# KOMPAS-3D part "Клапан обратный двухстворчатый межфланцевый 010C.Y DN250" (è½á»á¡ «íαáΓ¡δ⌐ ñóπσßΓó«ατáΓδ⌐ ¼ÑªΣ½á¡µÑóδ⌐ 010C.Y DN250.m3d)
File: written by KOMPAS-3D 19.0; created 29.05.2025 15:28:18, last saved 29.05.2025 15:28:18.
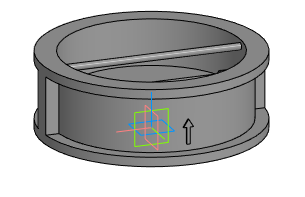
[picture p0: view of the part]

Document properties: Полное имя файла: E:\Dendor Работа Сачек\3D для проекитирвщиков\5.2 Тип 010C, 010C.Y Клапан обратный двухстворчатый межфланцевый\stp_Клапан обратный двухстворчатый межфланцевый 010C.Y\Клапан обратный двухстворчатый межфланцевый 010C.Y DN250.m3d

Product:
- Part/product: Клапан обратный двухстворчатый межфланцевый 010C.Y DN250

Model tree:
1. Операция без истории:1  (labels: Клапан обратный двухстворчатый межфланцевый 010C.Y DN250)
